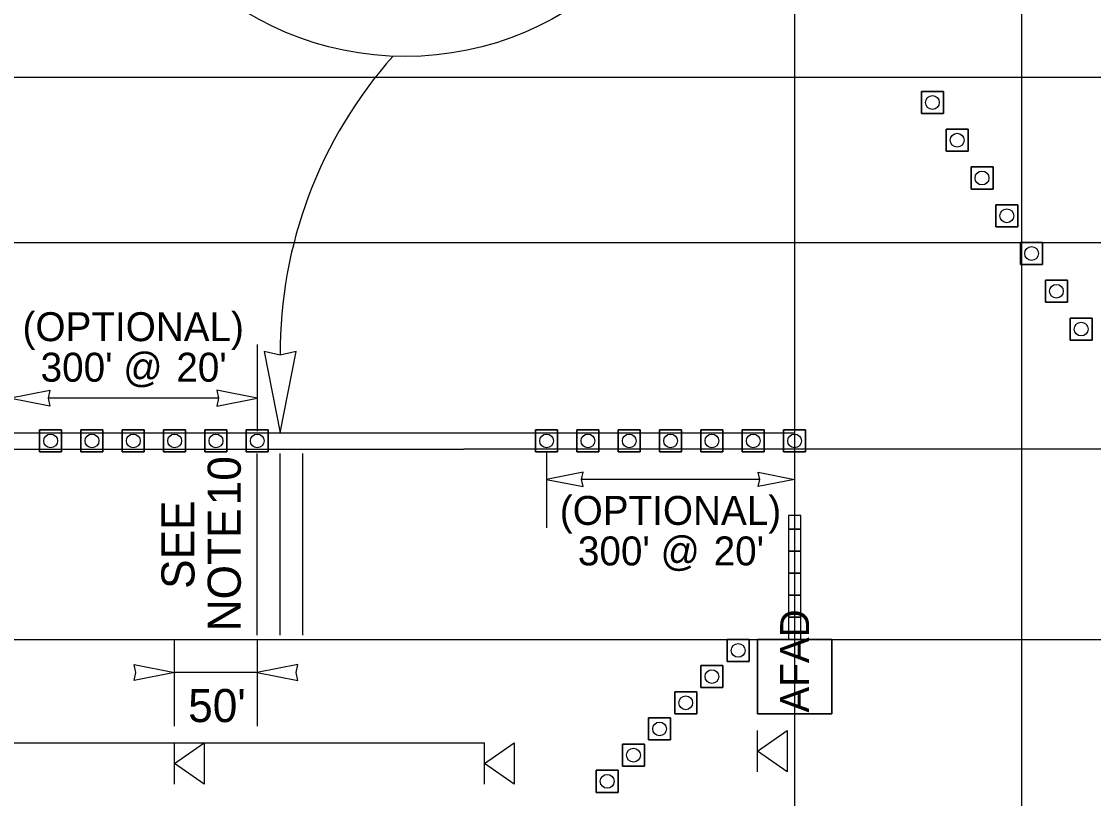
# Model space of a CAD drawing. Extents: x 99999.1 to 100095.7, y 99995 to 100010.7.
# Drawn here: x 100042.406 to 100045, y 100005.747 to 100007.627 of the extents above; entities that cross this region are included whole.
import ezdxf

# ---------------------------------------------------------------- set-up
doc = ezdxf.new("R2010")
doc.units = 0
for name, color, linetype in [('RD_ED_ShoulderPavedEdge', 7, 'Continuous'), ('RD_MK_LineDblYellowCenter', 7, 'Continuous'), ('RD_MK_LineEdgeWhite', 7, 'Continuous'), ('RD_MK_LineNoPass', 7, 'Continuous'), ('RD_MK_LineSkipCenter', 7, 'Continuous'), ('TR_WZ_AFAD', 7, 'Continuous'), ('TR_WZ_PortableSignMountBlk-Org', 7, 'Continuous'), ('TR_WZ_PortableSignMountBlk-Wht', 7, 'Continuous'), ('TR_WZ_TrafficCone', 7, 'Continuous'), ('TR_WZ_WorkZoneDetails', 7, 'Continuous'), ('TR_WZ_WorkZoneTextCurrent', 7, 'Continuous')]:
    doc.layers.add(name, color=color, linetype=linetype)

msp = doc.modelspace()

# ---------------------------------------------------------------- linework, layer by layer
at = {"layer": 'RD_ED_ShoulderPavedEdge'}
msp.add_line((100040.1076, 100007.4923), (100055.6424, 100007.4923), dxfattribs=at)
at = {"layer": 'RD_MK_LineDblYellowCenter'}
for p, q in [((100040.1282, 100006.6323), (100043.4767, 100006.6323)), ((100040.0869, 100006.5923), (100043.4767, 100006.5923))]:
    msp.add_line(p, q, dxfattribs=at)
at = {"layer": 'RD_MK_LineEdgeWhite'}
for p, q in [((100040.1076, 100007.0923), (100055.6424, 100007.0923)), ((100040.1076, 100006.1323), (100055.6424, 100006.1323))]:
    msp.add_line(p, q, dxfattribs=at)
at = {"layer": 'RD_MK_LineNoPass'}
msp.add_line((100043.4767, 100006.6323), (100044.2767, 100006.6323), dxfattribs=at)
at = {"layer": 'RD_MK_LineSkipCenter'}
msp.add_lwpolyline([(100051.15, 100006.5923), (100043.4767, 100006.5923)], dxfattribs=at)
at = {"layer": 'TR_WZ_AFAD'}
for p, q in [((100044.2916, 100006.399), (100044.2916, 100006.4323)), ((100044.2616, 100006.399), (100044.2616, 100006.3457)), ((100044.2616, 100006.399), (100044.2766, 100006.399)), ((100044.2766, 100006.399), (100044.2916, 100006.399)), ((100044.2916, 100006.3457), (100044.2916, 100006.399)), ((100044.2616, 100006.3457), (100044.2616, 100006.2923)), ((100044.2766, 100006.3457), (100044.2616, 100006.3457)), ((100044.2916, 100006.3457), (100044.2766, 100006.3457)), ((100044.2916, 100006.2923), (100044.2916, 100006.3457)), ((100044.2616, 100006.2923), (100044.2616, 100006.239)), ((100044.2616, 100006.2923), (100044.2766, 100006.2923)), ((100044.2766, 100006.2923), (100044.2916, 100006.2923)), ((100044.2916, 100006.239), (100044.2916, 100006.2923)), ((100044.2766, 100006.239), (100044.2616, 100006.239)), ((100044.2616, 100006.239), (100044.2616, 100006.1857)), ((100044.2916, 100006.239), (100044.2766, 100006.239)), ((100044.2916, 100006.1857), (100044.2916, 100006.239)), ((100044.2616, 100006.1857), (100044.2616, 100006.1323)), ((100044.1866, 100005.9523), (100044.1866, 100006.1323)), ((100044.1866, 100006.1323), (100044.3666, 100006.1323)), ((100044.27, 100006.1323), (100044.1866, 100006.1323)), ((100044.1866, 100006.1323), (100044.1866, 100005.9523)), ((100044.2616, 100006.1323), (100044.27, 100006.1323)), ((100044.27, 100006.1323), (100044.2766, 100006.1323)), ((100044.3666, 100006.1323), (100044.3666, 100005.9523)), ((100044.3666, 100005.9523), (100044.3666, 100006.1323)), ((100044.3666, 100005.9523), (100044.1866, 100005.9523)), ((100044.1866, 100005.9523), (100044.3666, 100005.9523))]:
    msp.add_line(p, q, dxfattribs=at)
for points in [[(100044.2916, 100006.4323), (100044.2616, 100006.4323), (100044.2616, 100006.399)], [(100044.2916, 100006.1323), (100044.2916, 100006.4323), (100044.2616, 100006.4323), (100044.2616, 100006.1323)], [(100044.2916, 100006.399), (100044.2766, 100006.399), (100044.2616, 100006.399)], [(100044.2616, 100006.3457), (100044.2766, 100006.3457), (100044.2916, 100006.3457)], [(100044.2916, 100006.2923), (100044.2766, 100006.2923), (100044.2616, 100006.2923)], [(100044.2616, 100006.239), (100044.2766, 100006.239), (100044.2916, 100006.239)], [(100044.2916, 100006.1857), (100044.2766, 100006.1857), (100044.2616, 100006.1857)], [(100044.2616, 100006.1857), (100044.2766, 100006.1857), (100044.2916, 100006.1857)], [(100044.2766, 100006.1323), (100044.2833, 100006.1323), (100044.2916, 100006.1323), (100044.2916, 100006.1857)], [(100044.3666, 100006.1323), (100044.2833, 100006.1323), (100044.27, 100006.1323)]]:
    msp.add_lwpolyline(points, dxfattribs=at)
at = {"layer": 'TR_WZ_PortableSignMountBlk-Org'}
for p, q in [((100042.7767, 100005.7824), (100042.7767, 100005.8824)), ((100043.5267, 100005.7824), (100043.5267, 100005.8824))]:
    msp.add_line(p, q, dxfattribs=at)
for points in [[(100042.7767, 100005.8323), (100042.8485, 100005.8824), (100042.8485, 100005.7824)], [(100043.5267, 100005.8323), (100043.5985, 100005.8824), (100043.5985, 100005.7824)]]:
    msp.add_lwpolyline(points, close=True, dxfattribs=at)
at = {"layer": 'TR_WZ_PortableSignMountBlk-Wht'}
msp.add_line((100044.1867, 100005.8123), (100044.1867, 100005.9123), dxfattribs=at)
msp.add_lwpolyline([(100044.1867, 100005.8622), (100044.2585, 100005.9123), (100044.2585, 100005.8123)], close=True, dxfattribs=at)
at = {"layer": 'TR_WZ_TrafficCone'}
for points in [[(100044.6367, 100007.4577), (100044.5834, 100007.4577), (100044.5834, 100007.4043), (100044.6367, 100007.4043), (100044.6367, 100007.4577)], [(100044.6367, 100007.4043), (100044.5834, 100007.4043), (100044.5834, 100007.4577), (100044.6367, 100007.4577), (100044.6367, 100007.4043)], [(100044.6967, 100007.3663), (100044.6434, 100007.3663), (100044.6434, 100007.313), (100044.6967, 100007.313), (100044.6967, 100007.3663)], [(100044.6967, 100007.313), (100044.6434, 100007.313), (100044.6434, 100007.3663), (100044.6967, 100007.3663), (100044.6967, 100007.313)], [(100044.7567, 100007.275), (100044.7034, 100007.275), (100044.7034, 100007.2217), (100044.7567, 100007.2217), (100044.7567, 100007.275)], [(100044.7567, 100007.2217), (100044.7034, 100007.2217), (100044.7034, 100007.275), (100044.7567, 100007.275), (100044.7567, 100007.2217)], [(100044.8167, 100007.1837), (100044.7634, 100007.1837), (100044.7634, 100007.1303), (100044.8167, 100007.1303), (100044.8167, 100007.1837)], [(100044.8167, 100007.1303), (100044.7634, 100007.1303), (100044.7634, 100007.1837), (100044.8167, 100007.1837), (100044.8167, 100007.1303)], [(100044.8234, 100007.0923), (100044.8767, 100007.0923), (100044.8767, 100007.039), (100044.8234, 100007.039), (100044.8234, 100007.0923)], [(100044.8234, 100007.039), (100044.8767, 100007.039), (100044.8767, 100007.0923), (100044.8234, 100007.0923), (100044.8234, 100007.039)], [(100044.8834, 100007.001), (100044.9367, 100007.001), (100044.9367, 100006.9477), (100044.8834, 100006.9477), (100044.8834, 100007.001)], [(100044.8834, 100006.9477), (100044.9367, 100006.9477), (100044.9367, 100007.001), (100044.8834, 100007.001), (100044.8834, 100006.9477)], [(100044.9434, 100006.9097), (100044.9967, 100006.9097), (100044.9967, 100006.8563), (100044.9434, 100006.8563), (100044.9434, 100006.9097)], [(100044.9434, 100006.8563), (100044.9967, 100006.8563), (100044.9967, 100006.9097), (100044.9434, 100006.9097), (100044.9434, 100006.8563)], [(100042.5033, 100006.639), (100042.45, 100006.639), (100042.45, 100006.5857), (100042.5033, 100006.5857), (100042.5033, 100006.639)], [(100042.5033, 100006.5857), (100042.45, 100006.5857), (100042.45, 100006.639), (100042.5033, 100006.639), (100042.5033, 100006.5857)], [(100042.6033, 100006.639), (100042.55, 100006.639), (100042.55, 100006.5857), (100042.6033, 100006.5857), (100042.6033, 100006.639)], [(100042.6033, 100006.5857), (100042.55, 100006.5857), (100042.55, 100006.639), (100042.6033, 100006.639), (100042.6033, 100006.5857)], [(100042.7033, 100006.639), (100042.65, 100006.639), (100042.65, 100006.5857), (100042.7033, 100006.5857), (100042.7033, 100006.639)], [(100042.7033, 100006.5857), (100042.65, 100006.5857), (100042.65, 100006.639), (100042.7033, 100006.639), (100042.7033, 100006.5857)], [(100042.8033, 100006.639), (100042.75, 100006.639), (100042.75, 100006.5857), (100042.8033, 100006.5857), (100042.8033, 100006.639)], [(100042.8033, 100006.5857), (100042.75, 100006.5857), (100042.75, 100006.639), (100042.8033, 100006.639), (100042.8033, 100006.5857)], [(100042.9033, 100006.639), (100042.85, 100006.639), (100042.85, 100006.5857), (100042.9033, 100006.5857), (100042.9033, 100006.639)], [(100042.9033, 100006.5857), (100042.85, 100006.5857), (100042.85, 100006.639), (100042.9033, 100006.639), (100042.9033, 100006.5857)], [(100043.0033, 100006.639), (100042.95, 100006.639), (100042.95, 100006.5857), (100043.0033, 100006.5857), (100043.0033, 100006.639)], [(100043.0033, 100006.5857), (100042.95, 100006.5857), (100042.95, 100006.639), (100043.0033, 100006.639), (100043.0033, 100006.5857)], [(100043.7033, 100006.639), (100043.65, 100006.639), (100043.65, 100006.5857), (100043.7033, 100006.5857), (100043.7033, 100006.639)], [(100043.7033, 100006.5857), (100043.65, 100006.5857), (100043.65, 100006.639), (100043.7033, 100006.639), (100043.7033, 100006.5857)], [(100043.8033, 100006.639), (100043.75, 100006.639), (100043.75, 100006.5857), (100043.8033, 100006.5857), (100043.8033, 100006.639)], [(100043.8033, 100006.5857), (100043.75, 100006.5857), (100043.75, 100006.639), (100043.8033, 100006.639), (100043.8033, 100006.5857)], [(100043.9033, 100006.639), (100043.85, 100006.639), (100043.85, 100006.5857), (100043.9033, 100006.5857), (100043.9033, 100006.639)], [(100043.9033, 100006.5857), (100043.85, 100006.5857), (100043.85, 100006.639), (100043.9033, 100006.639), (100043.9033, 100006.5857)], [(100044.0033, 100006.639), (100043.95, 100006.639), (100043.95, 100006.5857), (100044.0033, 100006.5857), (100044.0033, 100006.639)], [(100044.0033, 100006.5857), (100043.95, 100006.5857), (100043.95, 100006.639), (100044.0033, 100006.639), (100044.0033, 100006.5857)], [(100044.1033, 100006.639), (100044.05, 100006.639), (100044.05, 100006.5857), (100044.1033, 100006.5857), (100044.1033, 100006.639)], [(100044.1033, 100006.5857), (100044.05, 100006.5857), (100044.05, 100006.639), (100044.1033, 100006.639), (100044.1033, 100006.5857)], [(100044.2033, 100006.639), (100044.15, 100006.639), (100044.15, 100006.5857), (100044.2033, 100006.5857), (100044.2033, 100006.639)], [(100044.2033, 100006.5857), (100044.15, 100006.5857), (100044.15, 100006.639), (100044.2033, 100006.639), (100044.2033, 100006.5857)], [(100044.3033, 100006.639), (100044.25, 100006.639), (100044.25, 100006.5857), (100044.3033, 100006.5857), (100044.3033, 100006.639)], [(100044.3033, 100006.5857), (100044.25, 100006.5857), (100044.25, 100006.639), (100044.3033, 100006.639), (100044.3033, 100006.5857)], [(100044.1133, 100006.1323), (100044.1667, 100006.1323), (100044.1667, 100006.079), (100044.1133, 100006.079), (100044.1133, 100006.1323)], [(100044.1133, 100006.079), (100044.1667, 100006.079), (100044.1667, 100006.1323), (100044.1133, 100006.1323), (100044.1133, 100006.079)], [(100044.05, 100006.069), (100044.1033, 100006.069), (100044.1033, 100006.0157), (100044.05, 100006.0157), (100044.05, 100006.069)], [(100044.05, 100006.0157), (100044.1033, 100006.0157), (100044.1033, 100006.069), (100044.05, 100006.069), (100044.05, 100006.0157)], [(100043.9867, 100006.0057), (100044.04, 100006.0057), (100044.04, 100005.9523), (100043.9867, 100005.9523), (100043.9867, 100006.0057)], [(100043.9867, 100005.9523), (100044.04, 100005.9523), (100044.04, 100006.0057), (100043.9867, 100006.0057), (100043.9867, 100005.9523)], [(100043.9767, 100005.9423), (100043.9233, 100005.9423), (100043.9233, 100005.889), (100043.9767, 100005.889), (100043.9767, 100005.9423)], [(100043.9767, 100005.889), (100043.9233, 100005.889), (100043.9233, 100005.9423), (100043.9767, 100005.9423), (100043.9767, 100005.889)], [(100043.9133, 100005.879), (100043.86, 100005.879), (100043.86, 100005.8257), (100043.9133, 100005.8257), (100043.9133, 100005.879)], [(100043.9133, 100005.8257), (100043.86, 100005.8257), (100043.86, 100005.879), (100043.9133, 100005.879), (100043.9133, 100005.8257)], [(100043.85, 100005.8157), (100043.7967, 100005.8157), (100043.7967, 100005.7623), (100043.85, 100005.7623), (100043.85, 100005.8157)], [(100043.85, 100005.7623), (100043.7967, 100005.7623), (100043.7967, 100005.8157), (100043.85, 100005.8157), (100043.85, 100005.7623)]]:
    msp.add_lwpolyline(points, dxfattribs=at)
for centre in [(100044.61, 100007.431), (100044.67, 100007.3397), (100044.73, 100007.2483), (100044.79, 100007.157), (100044.85, 100007.0657), (100044.91, 100006.9743), (100044.97, 100006.883), (100042.4767, 100006.6123), (100042.5767, 100006.6123), (100042.6767, 100006.6123), (100042.7767, 100006.6123), (100042.8767, 100006.6123), (100042.9767, 100006.6123), (100043.6767, 100006.6123), (100043.7767, 100006.6123), (100043.8767, 100006.6123), (100043.9767, 100006.6123), (100044.0767, 100006.6123), (100044.1767, 100006.6123), (100044.2767, 100006.6123), (100044.14, 100006.1057), (100044.0767, 100006.0423), (100044.0133, 100005.979), (100043.95, 100005.9157), (100043.8867, 100005.8523), (100043.8233, 100005.789)]:
    msp.add_circle(centre, 0.0167, dxfattribs=at)
at = {"layer": 'TR_WZ_WorkZoneDetails'}
for p, q in [((100044.2767, 100008.7991), (100044.2767, 100005.4923)), ((100044.8267, 100005.4923), (100044.8267, 100007.7323)), ((100042.9767, 100006.8457), (100042.9767, 100006.6357)), ((100042.8829, 100006.7157), (100042.4704, 100006.7157)), ((100042.9767, 100006.1423), (100042.9767, 100006.5823)), ((100043.0323, 100006.1423), (100043.0323, 100006.5823)), ((100043.0872, 100006.1423), (100043.0872, 100006.5823)), ((100043.6767, 100006.5857), (100043.6767, 100006.4023)), ((100044.1923, 100006.5193), (100043.761, 100006.5193)), ((100042.7767, 100005.9223), (100042.7767, 100006.1323)), ((100042.9767, 100006.1323), (100042.9767, 100005.9223)), ((100042.9767, 100006.0523), (100042.7767, 100006.0523)), ((100040.5267, 100005.8824), (100043.5267, 100005.8824))]:
    msp.add_line(p, q, dxfattribs=at)
for points in [[(100043.0323, 100006.6323), (100043.0708, 100006.8289), (100043.0323, 100006.8198), (100042.9937, 100006.8289)], [(100042.3767, 100006.7157), (100042.4749, 100006.7349), (100042.4704, 100006.7157), (100042.4749, 100006.6964)], [(100042.9767, 100006.7157), (100042.8784, 100006.7349), (100042.8829, 100006.7157), (100042.8784, 100006.6964)], [(100043.6767, 100006.5193), (100043.7651, 100006.502), (100043.761, 100006.5193), (100043.7651, 100006.5367)], [(100044.2767, 100006.5193), (100044.1882, 100006.502), (100044.1923, 100006.5193), (100044.1882, 100006.5367)], [(100042.7767, 100006.0523), (100042.6784, 100006.0331), (100042.6829, 100006.0523), (100042.6784, 100006.0716)], [(100042.9767, 100006.0523), (100043.0749, 100006.0331), (100043.0704, 100006.0523), (100043.0749, 100006.0716)]]:
    msp.add_lwpolyline(points, close=True, dxfattribs=at)
msp.add_circle((100043.3346, 100008.2843), 0.742, dxfattribs=at)
msp.add_arc((100044.1081, 100006.8268), 1.0759, 138.2705, 180.3733, dxfattribs=at)

# ---------------------------------------------------------------- texts
at = {"layer": 'TR_WZ_AFAD'}
msp.add_text('AFAD', height=0.07, rotation=90, dxfattribs=at).set_placement((100044.3116, 100005.9553))
at = {"layer": 'TR_WZ_WorkZoneDetails'}
for s, p in [('10', (100042.9367, 100006.4566)), ('SEE', (100042.8247, 100006.2544)), ('NOTE', (100042.9367, 100006.1518))]:
    msp.add_text(s, height=0.08, rotation=90, dxfattribs=at).set_placement(p)
at = {"layer": 'TR_WZ_WorkZoneTextCurrent'}
for s, height, p in [('(OPTIONAL)', 0.07, (100042.4087, 100006.8537)), ("300' @", 0.07, (100042.4524, 100006.7557)), ("20'", 0.07, (100042.7808, 100006.7557)), ('(OPTIONAL)', 0.07, (100043.7085, 100006.4093)), ("300' @", 0.07, (100043.7523, 100006.3113)), ("20'", 0.07, (100044.0807, 100006.3113)), ("50'", 0.08, (100042.8094, 100005.9323))]:
    msp.add_text(s, height=height, dxfattribs=at).set_placement(p)

doc.saveas('drawing.dxf')
